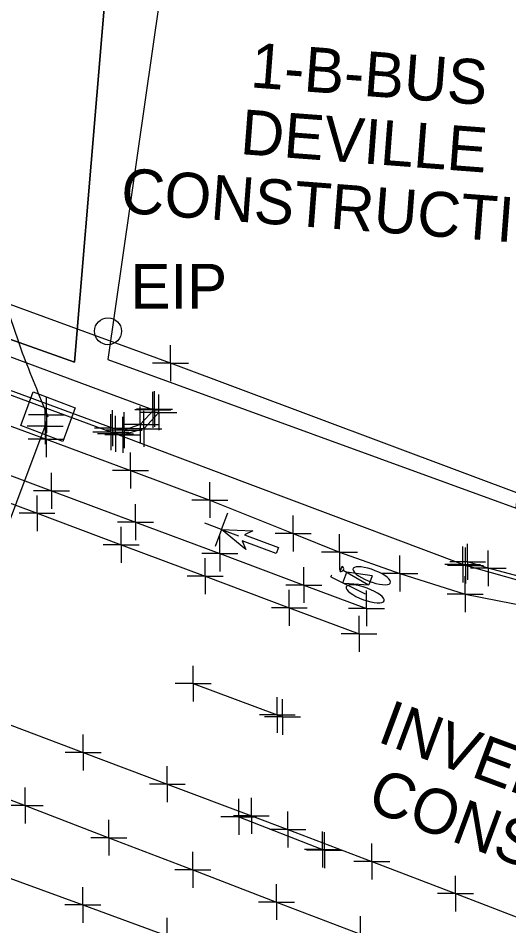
# Model space of a CAD drawing. Extents: x 0 to 1944463, y 0 to 420651.
# Drawn here: x 1942579.7 to 1942634.3, y 417899.8 to 418000.9 of the extents above; entities that cross this region are included whole.
import ezdxf

# ---------------------------------------------------------------- set-up
doc = ezdxf.new("R2010")
doc.units = 0
for name, color, linetype in [('SUR - DRG - Storm Sewer', 7, 'Continuous'), ('SUR - DRG - Storm Sewer - Points - Locators', 7, 'Continuous'), ('SUR - DRG - Storm Sewer Text', 7, 'Continuous'), ('SUR - DTM - Breaklines', 7, 'Continuous'), ('SUR - DTM - Breaklines - Points - Locators', 7, 'Continuous'), ('SUR - NON-TRAN - Buildings', 7, 'Continuous'), ('SUR - PROPERTY - Property Lines', 7, 'Continuous'), ('SUR - PROPERTY - Property Markers', 7, 'Continuous'), ('SUR - TR-CTRL - Pavement Marking', 7, 'Continuous'), ('SUR - TR-CTRL - Pavement Marking - Points - Locators', 7, 'Continuous'), ('SUR - TRAN - Features', 7, 'Continuous'), ('SUR - TRAN - Features - Points - Locators', 7, 'Continuous'), ('SUR - TRAN - Roads', 7, 'Continuous')]:
    doc.layers.add(name, color=color, linetype=linetype)

msp = doc.modelspace()

# ---------------------------------------------------------------- linework, layer by layer
at = {"layer": 'SUR - DRG - Storm Sewer'}
msp.add_line((1942583, 417956.5), (1942583, 417956.5), dxfattribs=at)
for points in [[(1942579.96, 417955.5), (1942581.36, 417959.25), (1942586.04, 417957.49), (1942584.64, 417953.75), (1942579.96, 417955.5)], [(1942553.81, 417878.43), (1942582.69, 417955.43)]]:
    msp.add_lwpolyline(points, dxfattribs=at)
at = {"layer": 'SUR - DRG - Storm Sewer - Points - Locators'}
for p, q in [((1942582.84, 417956.69), (1942582.84, 417958.69)), ((1942582.69, 417955.43), (1942582.69, 417957.43)), ((1942582.84, 417956.69), (1942580.84, 417956.69)), ((1942582.84, 417956.69), (1942584.84, 417956.69)), ((1942582.84, 417956.69), (1942582.84, 417954.69)), ((1942582.69, 417955.43), (1942580.69, 417955.43)), ((1942582.69, 417955.43), (1942584.69, 417955.43)), ((1942582.69, 417955.43), (1942582.69, 417953.43))]:
    msp.add_line(p, q, dxfattribs=at)
at = {"layer": 'SUR - DRG - Storm Sewer Text'}
msp.add_open_spline([(1942601.33, 418079.02), (1942615.68, 418060.65), (1942563.46, 418001.22), (1942583, 417956.5)], degree=2, dxfattribs=at)
at = {"layer": 'SUR - DTM - Breaklines'}
for points in [[(1942594.86, 417957.35), (1942593.26, 417955.62), (1942591.48, 417955), (1942590.18, 417955.23), (1942569.31, 417962.91)], [(1942685.3, 417955.86), (1942676.89, 417947.71), (1942666.59, 417941.57), (1942660.84, 417939.34), (1942656.51, 417938.36), (1942649.36, 417937.44), (1942636.62, 417938.4), (1942632.04, 417939.62), (1942629.74, 417940.35)], [(1942513.06, 417938.27), (1942522.46, 417934.85), (1942531.86, 417931.44), (1942541.26, 417928.02), (1942550.66, 417924.6), (1942552.44, 417923.95), (1942561.78, 417920.37), (1942571.11, 417916.79), (1942580.45, 417913.21), (1942589.79, 417909.63), (1942599.12, 417906.05), (1942608.46, 417902.47), (1942617.8, 417898.89), (1942627.14, 417895.31), (1942636.47, 417891.73), (1942645.81, 417888.15), (1942655.15, 417884.57), (1942664.48, 417880.99), (1942673.82, 417877.41), (1942683.16, 417873.83), (1942687.92, 417872.01), (1942697.21, 417868.31), (1942706.5, 417864.6), (1942715.79, 417860.9)]]:
    msp.add_lwpolyline(points, dxfattribs=at)
at = {"layer": 'SUR - DTM - Breaklines - Points - Locators'}
for p, q in [((1942594.86, 417957.35), (1942594.86, 417959.35)), ((1942594.86, 417957.35), (1942592.86, 417957.35)), ((1942593.26, 417955.62), (1942593.26, 417957.62)), ((1942594.86, 417957.35), (1942596.86, 417957.35)), ((1942594.86, 417957.35), (1942594.86, 417955.35)), ((1942590.18, 417955.23), (1942590.18, 417957.23)), ((1942591.48, 417955), (1942591.48, 417957)), ((1942593.26, 417955.62), (1942591.26, 417955.62)), ((1942593.26, 417955.62), (1942595.26, 417955.62)), ((1942593.26, 417955.62), (1942593.26, 417953.62)), ((1942590.18, 417955.23), (1942588.18, 417955.23)), ((1942591.48, 417955), (1942589.48, 417955)), ((1942590.18, 417955.23), (1942592.18, 417955.23)), ((1942590.18, 417955.23), (1942590.18, 417953.23)), ((1942591.48, 417955), (1942593.48, 417955)), ((1942591.48, 417955), (1942591.48, 417953)), ((1942629.74, 417940.35), (1942629.74, 417942.35)), ((1942632.04, 417939.62), (1942632.04, 417941.62)), ((1942629.74, 417940.35), (1942627.74, 417940.35)), ((1942629.74, 417940.35), (1942631.74, 417940.35)), ((1942629.74, 417940.35), (1942629.74, 417938.35)), ((1942632.04, 417939.62), (1942630.04, 417939.62)), ((1942632.04, 417939.62), (1942634.04, 417939.62)), ((1942632.04, 417939.62), (1942632.04, 417937.62)), ((1942580.45, 417913.21), (1942580.45, 417915.21)), ((1942580.45, 417913.21), (1942578.45, 417913.21)), ((1942580.45, 417913.21), (1942582.45, 417913.21)), ((1942580.45, 417913.21), (1942580.45, 417911.21)), ((1942589.79, 417909.63), (1942589.79, 417911.63)), ((1942589.79, 417909.63), (1942587.79, 417909.63)), ((1942589.79, 417909.63), (1942591.79, 417909.63)), ((1942589.79, 417909.63), (1942589.79, 417907.63)), ((1942599.12, 417906.05), (1942599.12, 417908.05)), ((1942599.12, 417906.05), (1942597.12, 417906.05)), ((1942599.12, 417906.05), (1942601.12, 417906.05)), ((1942599.12, 417906.05), (1942599.12, 417904.05)), ((1942608.46, 417902.47), (1942608.46, 417904.47)), ((1942608.46, 417902.47), (1942606.46, 417902.47)), ((1942608.46, 417902.47), (1942610.46, 417902.47)), ((1942608.46, 417902.47), (1942608.46, 417900.47)), ((1942617.8, 417898.89), (1942617.8, 417900.89))]:
    msp.add_line(p, q, dxfattribs=at)
at = {"layer": 'SUR - NON-TRAN - Buildings'}
for points in [[(1942529.1, 417982.77), (1942585.95, 417962.57), (1942590.94, 418021.99), (1942530.81, 418025.75)], [(1942529.1, 417982.77), (1942530.81, 418025.75), (1942590.94, 418021.99), (1942585.95, 417962.57)], [(1942589.66, 417962.87), (1942635.14, 417946.3), (1942637.72, 417970.25), (1942644.9, 417970.06), (1942646.09, 417985.83), (1942639.56, 417986.32), (1942641.7, 418014.59), (1942597.09, 418014.5)]]:
    msp.add_lwpolyline(points, close=True, dxfattribs=at)
at = {"layer": 'SUR - PROPERTY - Property Lines'}
for p, q in [((1942590.52, 417954.58), (1942590.52, 417956.58)), ((1942590.52, 417954.58), (1942588.52, 417954.58)), ((1942590.52, 417954.58), (1942592.52, 417954.58)), ((1942590.52, 417954.58), (1942590.52, 417952.58)), ((1942629.19, 417940.05), (1942629.19, 417942.05)), ((1942629.19, 417940.05), (1942627.19, 417940.05)), ((1942629.19, 417940.05), (1942631.19, 417940.05)), ((1942629.19, 417940.05), (1942629.19, 417938.05))]:
    msp.add_line(p, q, dxfattribs=at)
at = {"layer": 'SUR - PROPERTY - Property Markers'}
msp.add_circle((1942589.68, 417966.01), 1.5, dxfattribs=at)
at = {"layer": 'SUR - TR-CTRL - Pavement Marking'}
for p, q in [((1942605.05, 417941.73), (1942602.33, 417943.93)), ((1942602.33, 417943.93), (1942605.82, 417943.8)), ((1942605.82, 417943.8), (1942604.87, 417943.36)), ((1942604.87, 417943.36), (1942608.67, 417941.94)), ((1942608.41, 417941.26), (1942604.62, 417942.68)), ((1942604.62, 417942.68), (1942605.05, 417941.73)), ((1942608.67, 417941.94), (1942608.41, 417941.26)), ((1942615.54, 417939.28), (1942615.6, 417939.44)), ((1942615.6, 417939.45), (1942615.75, 417939.85)), ((1942615.6, 417939.44), (1942615.6, 417939.45)), ((1942615.85, 417938.02), (1942616.28, 417939.18)), ((1942615.89, 417939.4), (1942618.7, 417937.77)), ((1942619.09, 417938.78), (1942616.28, 417939.18)), ((1942614.52, 417938.68), (1942614.61, 417938.9)), ((1942614.52, 417938.68), (1942618.34, 417936.78)), ((1942619.09, 417938.78), (1942618.72, 417937.78)), ((1942615.99, 417937.95), (1942618.7, 417937.77))]:
    msp.add_line(p, q, dxfattribs=at)
for points in [[(1942485.28, 417990.1), (1942494.66, 417986.63), (1942504.03, 417983.15), (1942513.41, 417979.68), (1942518.19, 417977.91), (1942527.57, 417974.44), (1942536.95, 417970.96), (1942546.32, 417967.49), (1942554.67, 417964.4), (1942564.05, 417960.92), (1942573.42, 417957.45), (1942582.8, 417953.98), (1942592.18, 417950.5), (1942601.04, 417947.22), (1942610.31, 417943.49), (1942615.47, 417941.42), (1942622.2, 417939.05), (1942629.46, 417936.74), (1942645.59, 417933.58)], [(1942482.7, 417982.8), (1942492.07, 417979.3), (1942501.44, 417975.79), (1942510.8, 417972.29), (1942520.17, 417968.79), (1942529.53, 417965.28), (1942538.9, 417961.78), (1942544.32, 417959.75), (1942553.68, 417956.25), (1942563.05, 417952.75), (1942572.42, 417949.24), (1942581.78, 417945.74), (1942591.15, 417942.24), (1942600.51, 417938.73), (1942609.88, 417935.23), (1942617.64, 417932.33)], [(1942510.92, 417947.44), (1942520.3, 417943.95), (1942529.67, 417940.46), (1942539.04, 417936.98), (1942548.41, 417933.49), (1942557.78, 417930), (1942567.16, 417926.52), (1942576.53, 417923.03), (1942577.57, 417922.64), (1942586.93, 417919.12), (1942596.29, 417915.6), (1942605.65, 417912.07), (1942609.72, 417910.54), (1942619.06, 417906.97), (1942628.4, 417903.4), (1942637.74, 417899.83), (1942647.09, 417896.26), (1942655.19, 417893.17), (1942664.54, 417889.6), (1942673.88, 417886.03), (1942683.22, 417882.46), (1942691.75, 417879.2)], [(1942509.2, 417930.57), (1942518.59, 417927.13), (1942527.98, 417923.69), (1942537.37, 417920.26), (1942539.92, 417919.33), (1942549.31, 417915.89), (1942558.7, 417912.45), (1942568.09, 417909.02), (1942577.48, 417905.58), (1942586.87, 417902.14), (1942596.26, 417898.71), (1942605.65, 417895.27), (1942615.04, 417891.83), (1942618.78, 417890.46), (1942628.14, 417886.93), (1942637.5, 417883.41), (1942646.85, 417879.88), (1942656.21, 417876.35), (1942664.42, 417873.25), (1942673.73, 417869.61), (1942683.04, 417865.96), (1942688.88, 417863.68)], [(1942599.16, 417926.78), (1942608.54, 417923.29), (1942609.12, 417923.07)], [(1942604.24, 417911.95), (1942613.57, 417908.33), (1942613.79, 417908.24)]]:
    msp.add_lwpolyline(points, dxfattribs=at)
msp.add_arc((1942615.63, 417939.57), 0.306, 252.6145, 66.2584, dxfattribs=at)
for centre, major_axis, ratio, start_param, end_param in [((1942619.06, 417938.79), (-2.08, 0.78), 0.302542, 1.700921, 7.971867), ((1942618.33, 417936.77), (-2.11, 0.79), 0.298889, 1.386374, 7.660383), ((1942619.06, 417938.79), (-2.08, 0.78), 0.302542, 1.688682, 1.700921), ((1942618.33, 417936.77), (-2.11, 0.79), 0.298889, 1.377198, 1.386374)]:
    msp.add_ellipse(centre, major_axis=major_axis, ratio=ratio, start_param=start_param, end_param=end_param, dxfattribs=at)
at = {"layer": 'SUR - TR-CTRL - Pavement Marking - Points - Locators'}
for p, q in [((1942582.8, 417953.98), (1942582.8, 417955.98)), ((1942582.8, 417953.98), (1942580.8, 417953.98)), ((1942582.8, 417953.98), (1942584.8, 417953.98)), ((1942582.8, 417953.98), (1942582.8, 417951.98)), ((1942592.18, 417950.5), (1942592.18, 417952.5)), ((1942592.18, 417950.5), (1942590.18, 417950.5)), ((1942592.18, 417950.5), (1942594.18, 417950.5)), ((1942592.18, 417950.5), (1942592.18, 417948.5)), ((1942601.04, 417947.22), (1942601.04, 417949.22)), ((1942581.78, 417945.74), (1942581.78, 417947.74)), ((1942601.04, 417947.22), (1942599.04, 417947.22)), ((1942601.04, 417947.22), (1942603.04, 417947.22)), ((1942601.04, 417947.22), (1942601.04, 417945.22)), ((1942581.78, 417945.74), (1942579.78, 417945.74)), ((1942581.78, 417945.74), (1942583.78, 417945.74)), ((1942581.78, 417945.74), (1942581.78, 417943.74)), ((1942602.33, 417943.93), (1942603.04, 417945.8)), ((1942610.31, 417943.49), (1942610.31, 417945.49)), ((1942591.15, 417942.24), (1942591.15, 417944.24)), ((1942602.33, 417943.93), (1942600.46, 417944.63)), ((1942602.33, 417943.93), (1942601.63, 417942.05)), ((1942602.33, 417943.93), (1942604.21, 417943.22)), ((1942610.31, 417943.49), (1942608.31, 417943.49)), ((1942610.31, 417943.49), (1942612.31, 417943.49)), ((1942610.31, 417943.49), (1942610.31, 417941.49)), ((1942615.47, 417941.42), (1942615.47, 417943.42)), ((1942591.15, 417942.24), (1942589.15, 417942.24)), ((1942591.15, 417942.24), (1942593.15, 417942.24)), ((1942591.15, 417942.24), (1942591.15, 417940.24)), ((1942615.47, 417941.42), (1942613.47, 417941.42)), ((1942615.47, 417941.42), (1942617.47, 417941.42)), ((1942615.47, 417941.42), (1942615.47, 417939.42)), ((1942600.51, 417938.73), (1942600.51, 417940.73)), ((1942622.2, 417939.05), (1942622.2, 417941.05)), ((1942600.51, 417938.73), (1942598.51, 417938.73)), ((1942600.51, 417938.73), (1942602.51, 417938.73)), ((1942600.51, 417938.73), (1942600.51, 417936.73)), ((1942622.2, 417939.05), (1942620.2, 417939.05)), ((1942622.2, 417939.05), (1942624.2, 417939.05)), ((1942622.2, 417939.05), (1942622.2, 417937.05)), ((1942629.46, 417936.74), (1942629.46, 417938.74)), ((1942609.88, 417935.23), (1942609.88, 417937.23)), ((1942629.46, 417936.74), (1942627.46, 417936.74)), ((1942629.46, 417936.74), (1942631.46, 417936.74)), ((1942629.46, 417936.74), (1942629.46, 417934.74)), ((1942609.88, 417935.23), (1942607.88, 417935.23)), ((1942609.88, 417935.23), (1942611.88, 417935.23)), ((1942609.88, 417935.23), (1942609.88, 417933.23)), ((1942617.64, 417932.33), (1942617.64, 417934.33)), ((1942617.64, 417932.33), (1942615.64, 417932.33)), ((1942617.64, 417932.33), (1942619.64, 417932.33)), ((1942617.64, 417932.33), (1942617.64, 417930.33)), ((1942599.16, 417926.78), (1942599.16, 417928.78)), ((1942599.16, 417926.78), (1942597.16, 417926.78)), ((1942599.16, 417926.78), (1942601.16, 417926.78)), ((1942599.16, 417926.78), (1942599.16, 417924.78)), ((1942608.54, 417923.29), (1942608.54, 417925.29)), ((1942609.12, 417923.07), (1942609.12, 417925.07)), ((1942608.54, 417923.29), (1942606.54, 417923.29)), ((1942609.12, 417923.07), (1942607.12, 417923.07)), ((1942608.54, 417923.29), (1942610.54, 417923.29)), ((1942608.54, 417923.29), (1942608.54, 417921.29)), ((1942609.12, 417923.07), (1942611.12, 417923.07)), ((1942609.12, 417923.07), (1942609.12, 417921.07)), ((1942586.93, 417919.12), (1942586.93, 417921.12)), ((1942586.93, 417919.12), (1942584.93, 417919.12)), ((1942586.93, 417919.12), (1942588.93, 417919.12)), ((1942586.93, 417919.12), (1942586.93, 417917.12)), ((1942596.29, 417915.6), (1942596.29, 417917.6)), ((1942596.29, 417915.6), (1942594.29, 417915.6)), ((1942596.29, 417915.6), (1942598.29, 417915.6)), ((1942596.29, 417915.6), (1942596.29, 417913.6)), ((1942604.24, 417911.95), (1942604.24, 417913.95)), ((1942605.65, 417912.07), (1942605.65, 417914.07)), ((1942604.24, 417911.95), (1942602.24, 417911.95)), ((1942605.65, 417912.07), (1942603.65, 417912.07)), ((1942604.24, 417911.95), (1942606.24, 417911.95)), ((1942604.24, 417911.95), (1942604.24, 417909.95)), ((1942605.65, 417912.07), (1942607.65, 417912.07)), ((1942605.65, 417912.07), (1942605.65, 417910.07)), ((1942609.72, 417910.54), (1942609.72, 417912.54)), ((1942609.72, 417910.54), (1942607.72, 417910.54)), ((1942609.72, 417910.54), (1942611.72, 417910.54)), ((1942609.72, 417910.54), (1942609.72, 417908.54)), ((1942613.57, 417908.33), (1942613.57, 417910.33)), ((1942613.79, 417908.24), (1942613.79, 417910.24)), ((1942619.06, 417906.97), (1942619.06, 417908.97)), ((1942613.57, 417908.33), (1942611.57, 417908.33)), ((1942613.79, 417908.24), (1942611.79, 417908.24)), ((1942613.57, 417908.33), (1942615.57, 417908.33)), ((1942613.57, 417908.33), (1942613.57, 417906.33)), ((1942613.79, 417908.24), (1942615.79, 417908.24)), ((1942613.79, 417908.24), (1942613.79, 417906.24)), ((1942619.06, 417906.97), (1942617.06, 417906.97)), ((1942619.06, 417906.97), (1942621.06, 417906.97)), ((1942619.06, 417906.97), (1942619.06, 417904.97)), ((1942628.4, 417903.4), (1942628.4, 417905.4)), ((1942586.87, 417902.14), (1942586.87, 417904.14)), ((1942628.4, 417903.4), (1942626.4, 417903.4)), ((1942628.4, 417903.4), (1942630.4, 417903.4)), ((1942628.4, 417903.4), (1942628.4, 417901.4)), ((1942586.87, 417902.14), (1942584.87, 417902.14)), ((1942586.87, 417902.14), (1942588.87, 417902.14)), ((1942586.87, 417902.14), (1942586.87, 417900.14)), ((1942596.26, 417898.71), (1942596.26, 417900.71))]:
    msp.add_line(p, q, dxfattribs=at)
at = {"layer": 'SUR - TRAN - Features'}
for points in [[(1942681.17, 417959.38), (1942673.9, 417952.43), (1942663.95, 417947.51), (1942659.16, 417946.2), (1942648.81, 417945.32), (1942636.69, 417947.47), (1942596.65, 417962.46), (1942571.45, 417971.67), (1942525.79, 417989.29)], [(1942483.78, 417985.45), (1942493.15, 417981.95), (1942502.52, 417978.45), (1942511.89, 417974.95), (1942521.26, 417971.46), (1942525.71, 417969.79), (1942535.08, 417966.29), (1942544.45, 417962.8), (1942553.82, 417959.3), (1942563.19, 417955.8), (1942564.66, 417955.25), (1942574.03, 417951.75), (1942583.4, 417948.25), (1942592.76, 417944.76), (1942602.13, 417941.26), (1942611.5, 417937.76), (1942618.47, 417935.16)], [(1942594.67, 417957.26), (1942570.34, 417966.29), (1942569.24, 417963.05)], [(1942595.34, 417956.98), (1942593.69, 417955.16), (1942591.34, 417954.48), (1942590.01, 417954.76), (1942569.06, 417962.51)], [(1942685.75, 417955.58), (1942677.27, 417947.29), (1942666.72, 417941.06), (1942660.94, 417938.86), (1942656.5, 417937.78), (1942649.44, 417936.94), (1942636.75, 417937.88), (1942629.5, 417939.94)]]:
    msp.add_lwpolyline(points, dxfattribs=at)
at = {"layer": 'SUR - TRAN - Features - Points - Locators'}
for p, q in [((1942596.65, 417962.46), (1942596.65, 417964.46)), ((1942596.65, 417962.46), (1942594.65, 417962.46)), ((1942596.65, 417962.46), (1942598.65, 417962.46)), ((1942596.65, 417962.46), (1942596.65, 417960.46)), ((1942594.67, 417957.26), (1942594.67, 417959.26)), ((1942595.34, 417956.98), (1942595.34, 417958.98)), ((1942590.01, 417954.76), (1942590.01, 417956.76)), ((1942591.34, 417954.48), (1942591.34, 417956.48)), ((1942594.67, 417957.26), (1942592.67, 417957.26)), ((1942595.34, 417956.98), (1942593.34, 417956.98)), ((1942593.69, 417955.16), (1942593.69, 417957.16)), ((1942594.67, 417957.26), (1942596.67, 417957.26)), ((1942594.67, 417957.26), (1942594.67, 417955.26)), ((1942595.34, 417956.98), (1942597.34, 417956.98)), ((1942595.34, 417956.98), (1942595.34, 417954.98)), ((1942590.01, 417954.76), (1942588.01, 417954.76)), ((1942591.34, 417954.48), (1942589.34, 417954.48)), ((1942590.01, 417954.76), (1942592.01, 417954.76)), ((1942590.01, 417954.76), (1942590.01, 417952.76)), ((1942591.34, 417954.48), (1942593.34, 417954.48)), ((1942591.34, 417954.48), (1942591.34, 417952.48)), ((1942593.69, 417955.16), (1942591.69, 417955.16)), ((1942593.69, 417955.16), (1942595.69, 417955.16)), ((1942593.69, 417955.16), (1942593.69, 417953.16)), ((1942583.4, 417948.25), (1942583.4, 417950.25)), ((1942583.4, 417948.25), (1942581.4, 417948.25)), ((1942583.4, 417948.25), (1942585.4, 417948.25)), ((1942583.4, 417948.25), (1942583.4, 417946.25)), ((1942592.76, 417944.76), (1942592.76, 417946.76)), ((1942592.76, 417944.76), (1942590.76, 417944.76)), ((1942592.76, 417944.76), (1942594.76, 417944.76)), ((1942592.76, 417944.76), (1942592.76, 417942.76)), ((1942602.13, 417941.26), (1942602.13, 417943.26)), ((1942602.13, 417941.26), (1942600.13, 417941.26)), ((1942602.13, 417941.26), (1942604.13, 417941.26)), ((1942602.13, 417941.26), (1942602.13, 417939.26)), ((1942629.5, 417939.94), (1942629.5, 417941.94)), ((1942611.5, 417937.76), (1942611.5, 417939.76)), ((1942629.5, 417939.94), (1942627.5, 417939.94)), ((1942629.5, 417939.94), (1942631.5, 417939.94)), ((1942629.5, 417939.94), (1942629.5, 417937.94)), ((1942611.5, 417937.76), (1942609.5, 417937.76)), ((1942611.5, 417937.76), (1942613.5, 417937.76)), ((1942611.5, 417937.76), (1942611.5, 417935.76)), ((1942618.47, 417935.16), (1942618.47, 417937.16)), ((1942618.47, 417935.16), (1942616.47, 417935.16)), ((1942618.47, 417935.16), (1942620.47, 417935.16)), ((1942618.47, 417935.16), (1942618.47, 417933.16))]:
    msp.add_line(p, q, dxfattribs=at)
at = {"layer": 'SUR - TRAN - Roads'}
msp.add_lwpolyline([(1942629.19, 417940.05), (1942590.52, 417954.58)], dxfattribs=at)

# ---------------------------------------------------------------- texts
at = {"layer": 'SUR - DRG - Storm Sewer Text'}
for s, p in [('INVERTS FROM', (1942619.53, 417920.37)), (' CONST. PLANS', (1942616.6, 417913.46))]:
    msp.add_text(s, height=5, rotation=339.6219, dxfattribs=at).set_placement(p)
at = {"layer": 'SUR - NON-TRAN - Buildings'}
for s, p in [('1-B-BUS', (1942605.46, 417993.17)), ('DEVILLE', (1942604.32, 417985.74)), (' CONSTRUCTION', (1942589.15, 417979.36))]:
    msp.add_text(s, height=5, rotation=355.6678, dxfattribs=at).set_placement(p)
at = {"layer": 'SUR - PROPERTY - Property Markers'}
msp.add_text('EIP', height=5, dxfattribs=at).set_placement((1942592.18, 417968.51))

doc.saveas('drawing.dxf')
